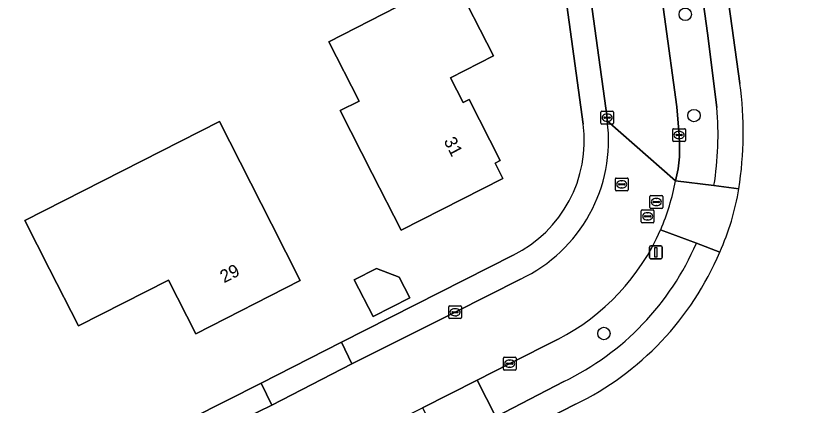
# Model space of a CAD drawing. Extents: x 162722 to 165104, y 384719 to 386284.
# Drawn here: x 164061.9 to 164123.8, y 385023.1 to 385053.7 of the extents above; entities that cross this region are included whole.
import ezdxf

# ---------------------------------------------------------------- set-up
doc = ezdxf.new("R2010")
doc.units = 0
for name, color, linetype in [('IMGEO_Boom', 7, 'Continuous'), ('IMGEO_Erf', 7, 'Continuous'), ('IMGEO_Groenvoorziening', 7, 'Continuous'), ('IMGEO_Kolk', 7, 'Continuous'), ('IMGEO_Lichtmast', 7, 'Continuous'), ('IMGEO_Pand', 7, 'Continuous'), ('IMGEO_Pand_nummerreeks', 7, 'Continuous'), ('IMGEO_Parkeervlak_open', 7, 'Continuous'), ('IMGEO_Rijbaan_lokaal_open', 7, 'Continuous'), ('IMGEO_Rioolput', 7, 'Continuous'), ('IMGEO_Voetpad_open', 7, 'Continuous')]:
    doc.layers.add(name, color=color, linetype=linetype)

msp = doc.modelspace()

# ---------------------------------------------------------------- linework, layer by layer
at = {"layer": 'IMGEO_Boom'}
for centre in [(164114.559, 385053.8), (164115.243, 385045.851), (164108.168, 385028.736)]:
    msp.add_circle(centre, 0.489, dxfattribs=at)
at = {"layer": 'IMGEO_Erf'}
for points in [[(164163.257, 385048.667), (164153.955, 385115.885), (164147.888, 385159.149), (164138.564, 385158), (164106.097, 385141.08), (164107.204, 385132.889), (164107.861, 385128.069), (164109.929, 385113.435), (164111.013, 385105.498), (164114.568, 385079.483), (164115.377, 385073.493), (164118.85, 385048.373)], [(164106.536, 385045.173), (164104.891, 385057.208)], [(164045.615, 385006.994), (164045.661, 385006.844), (164057.382, 385012.776), (164064.675, 385016.487), (164081.225, 385024.845), (164087.541, 385028.05), (164101.037, 385034.899)], [(164105.943, 385023.18), (164100.563, 385020.442), (164096.277, 385018.243), (164085.388, 385012.719), (164080.225, 385010.11), (164060.269, 385000), (164056.001, 384997.838), (164051.623, 384995.596), (164027.937, 384983.596), (164021.461, 384980.283), (164001.447, 384970.146), (164000, 384969.419), (163995.555, 384967.187), (163991.381, 384965.08), (163982.898, 384961.628)]]:
    msp.add_lwpolyline(points, dxfattribs=at)
for points in [[(164086.555, 385051.648), (164091.931, 385054.383), (164096.387, 385056.649), (164099.494, 385050.541), (164096.118, 385048.824), (164097.107, 385046.88), (164097.581, 385047.121), (164100.028, 385042.31), (164099.622, 385042.103), (164100.224, 385040.92), (164092.225, 385036.851), (164089.958, 385041.308), (164087.45, 385046.24), (164088.924, 385046.99)], [(164077.954, 385045.391), (164082.043, 385037.351), (164084.31, 385032.894), (164076.09, 385028.713), (164073.946, 385032.929), (164066.882, 385029.336), (164064.615, 385033.793), (164062.669, 385037.617)], [(164088.556, 385032.943), (164090.3, 385033.83), (164092.09, 385033.167), (164092.92, 385031.535), (164090.023, 385030.06)]]:
    msp.add_lwpolyline(points, close=True, dxfattribs=at)
for centre, radius, start, end in [((164090.657, 385044.517), 28.455, 351.0633, 7.7875), ((164096.613, 385043.876), 10.008, 296.23784, 7.44771), ((164099.205, 385043.286), 19.821, 335.69148, 350.74088), ((164095.684, 385044.246), 23.431, 295.96562, 337.09639)]:
    msp.add_arc(centre, radius, start, end, dxfattribs=at)
at = {"layer": 'IMGEO_Groenvoorziening'}
for points in [[(164117.043, 385046.479), (164116.295, 385052.312), (164113.428, 385073.243), (164110.323, 385072.813), (164111.956, 385060.695), (164113.896, 385046.54), (164114.074, 385044.319), (164114.117, 385043.575), (164114.097, 385042.613), (164113.99, 385041.657), (164113.799, 385040.714), (164116.814, 385040.352)], [(164115.441, 385035.835), (164112.627, 385036.876)], [(164104.574, 385028.285), (164100.766, 385026.367), (164098.211, 385025.06), (164099.678, 385022.179), (164105.03, 385024.959)]]:
    msp.add_lwpolyline(points, dxfattribs=at)
for centre, radius, start, end in [((164092.131, 385044.342), 25.003, 350.81686, 4.90221), ((164096.389, 385044.027), 17.743, 297.4715, 336.23127), ((164095.584, 385044.422), 21.634, 295.88866, 336.61412)]:
    msp.add_arc(centre, radius, start, end, dxfattribs=at)
at = {"layer": 'IMGEO_Kolk'}
for p, q in [((164107.924, 385045.26), (164107.924, 385046.112)), ((164107.999, 385046.186), (164108.851, 385046.186)), ((164108.183, 385045.68), (164108.183, 385045.692)), ((164108.226, 385045.729), (164108.624, 385045.729)), ((164108.412, 385045.966), (164108.437, 385045.966)), ((164108.667, 385045.692), (164108.667, 385045.68)), ((164108.925, 385046.112), (164108.925, 385045.26)), ((164108.851, 385045.186), (164107.999, 385045.186)), ((164108.621, 385045.643), (164108.223, 385045.643)), ((164108.435, 385045.406), (164108.41, 385045.406)), ((164113.573, 385043.893), (164113.573, 385044.745)), ((164113.648, 385044.819), (164114.5, 385044.819)), ((164114.061, 385044.599), (164114.086, 385044.599)), ((164114.574, 385044.745), (164114.574, 385043.893)), ((164114.5, 385043.819), (164113.648, 385043.819)), ((164113.832, 385044.313), (164113.832, 385044.325)), ((164114.27, 385044.276), (164113.872, 385044.276)), ((164113.875, 385044.362), (164114.273, 385044.362)), ((164114.084, 385044.039), (164114.059, 385044.039)), ((164114.316, 385044.325), (164114.316, 385044.313)), ((164095.97, 385029.979), (164095.97, 385030.831)), ((164096.045, 385030.905), (164096.897, 385030.905)), ((164096.971, 385030.831), (164096.971, 385029.979)), ((164096.229, 385030.399), (164096.229, 385030.411)), ((164096.667, 385030.362), (164096.269, 385030.362)), ((164096.272, 385030.448), (164096.67, 385030.448)), ((164096.458, 385030.685), (164096.483, 385030.685)), ((164096.713, 385030.411), (164096.713, 385030.399)), ((164096.897, 385029.905), (164096.045, 385029.905)), ((164096.481, 385030.125), (164096.456, 385030.125)), ((164100.265, 385025.941), (164100.265, 385026.793)), ((164100.34, 385026.867), (164101.192, 385026.867)), ((164100.753, 385026.647), (164100.778, 385026.647)), ((164101.266, 385026.793), (164101.266, 385025.941)), ((164100.524, 385026.361), (164100.524, 385026.373)), ((164100.962, 385026.324), (164100.564, 385026.324)), ((164100.567, 385026.41), (164100.965, 385026.41)), ((164100.776, 385026.087), (164100.751, 385026.087)), ((164101.008, 385026.373), (164101.008, 385026.361)), ((164101.192, 385025.867), (164100.34, 385025.867))]:
    msp.add_line(p, q, dxfattribs=at)
for points in [[(164107.924, 385045.26), (164107.924, 385046.112)], [(164107.999, 385046.186), (164108.851, 385046.186)], [(164108.925, 385046.112), (164108.925, 385045.26)], [(164108.851, 385045.186), (164107.999, 385045.186)], [(164113.573, 385043.893), (164113.573, 385044.745)], [(164113.648, 385044.819), (164114.5, 385044.819)], [(164114.574, 385044.745), (164114.574, 385043.893)], [(164114.5, 385043.819), (164113.648, 385043.819)], [(164095.97, 385029.979), (164095.97, 385030.831)], [(164096.045, 385030.905), (164096.897, 385030.905)], [(164096.971, 385030.831), (164096.971, 385029.979)], [(164096.897, 385029.905), (164096.045, 385029.905)], [(164100.265, 385025.941), (164100.265, 385026.793)], [(164100.34, 385026.867), (164101.192, 385026.867)], [(164101.266, 385026.793), (164101.266, 385025.941)], [(164101.192, 385025.867), (164100.34, 385025.867)]]:
    msp.add_lwpolyline(points, dxfattribs=at)
for centre, radius, start, end in [((164108.001, 385046.11), 0.0765, 91.55205, 178.44795), ((164108.001, 385046.11), 0.0765, 91.55205, 178.44795), ((164108.223, 385045.689), 0.0403, 85.87752, 175.75265), ((164108.22, 385045.679), 0.0366, 178.93798, 274.71019), ((164108.624, 385045.686), 0.043, 264.86636, 352.45326), ((164108.628, 385045.691), 0.0386, 1.73085, 96.63898), ((164108.849, 385046.11), 0.0765, 1.55205, 88.44795), ((164108.849, 385046.11), 0.0765, 1.55205, 88.44795), ((164108.001, 385045.262), 0.0765, 181.55205, 268.44795), ((164108.001, 385045.262), 0.0765, 181.55205, 268.44795), ((164108.849, 385045.262), 0.0765, 271.55205, 358.44795), ((164108.849, 385045.262), 0.0765, 271.55205, 358.44795), ((164113.65, 385044.743), 0.0765, 91.55205, 178.44795), ((164113.65, 385044.743), 0.0765, 91.55205, 178.44795), ((164114.498, 385044.743), 0.0765, 1.55205, 88.44795), ((164114.498, 385044.743), 0.0765, 1.55205, 88.44795), ((164113.65, 385043.895), 0.0765, 181.55205, 268.44795), ((164113.65, 385043.895), 0.0765, 181.55205, 268.44795), ((164113.872, 385044.322), 0.0403, 85.87752, 175.75265), ((164113.869, 385044.312), 0.0366, 178.93798, 274.71019), ((164114.273, 385044.319), 0.043, 264.86636, 352.45326), ((164114.277, 385044.324), 0.0386, 1.73085, 96.63898), ((164114.498, 385043.895), 0.0765, 271.55205, 358.44795), ((164114.498, 385043.895), 0.0765, 271.55205, 358.44795), ((164096.047, 385030.829), 0.0765, 91.55205, 178.44795), ((164096.047, 385030.829), 0.0765, 91.55205, 178.44795), ((164096.895, 385030.829), 0.0765, 1.55205, 88.44795), ((164096.895, 385030.829), 0.0765, 1.55205, 88.44795), ((164096.269, 385030.408), 0.0403, 85.87752, 175.75265), ((164096.266, 385030.398), 0.0366, 178.93798, 274.71019), ((164096.67, 385030.405), 0.043, 264.86636, 352.45326), ((164096.674, 385030.41), 0.0386, 1.73085, 96.63898), ((164096.047, 385029.981), 0.0765, 181.55205, 268.44795), ((164096.047, 385029.981), 0.0765, 181.55205, 268.44795), ((164096.895, 385029.981), 0.0765, 271.55205, 358.44795), ((164096.895, 385029.981), 0.0765, 271.55205, 358.44795), ((164100.342, 385026.791), 0.0765, 91.55205, 178.44795), ((164100.342, 385026.791), 0.0765, 91.55205, 178.44795), ((164101.19, 385026.791), 0.0765, 1.55205, 88.44795), ((164101.19, 385026.791), 0.0765, 1.55205, 88.44795), ((164100.342, 385025.943), 0.0765, 181.55205, 268.44795), ((164100.342, 385025.943), 0.0765, 181.55205, 268.44795), ((164100.564, 385026.37), 0.0403, 85.87752, 175.75265), ((164100.561, 385026.36), 0.0366, 178.93798, 274.71019), ((164100.965, 385026.367), 0.043, 264.86636, 352.45326), ((164100.969, 385026.372), 0.0386, 1.73085, 96.63898), ((164101.19, 385025.943), 0.0765, 271.55205, 358.44795), ((164101.19, 385025.943), 0.0765, 271.55205, 358.44795)]:
    msp.add_arc(centre, radius, start, end, dxfattribs=at)
for centre, major_axis, ratio, start_param, end_param in [((164108.411, 385045.686), (-0.387, 0.002), 0.722429, 4.712389, 7.853982), ((164108.436, 385045.686), (-0.39, 0.002), 0.717154, 1.570796, 4.712389), ((164114.06, 385044.319), (-0.387, 0.002), 0.722429, 4.712389, 7.853982), ((164114.085, 385044.319), (-0.39, 0.002), 0.717154, 1.570796, 4.712389), ((164096.457, 385030.405), (-0.387, 0.002), 0.722429, 4.712389, 7.853982), ((164096.482, 385030.405), (-0.39, 0.002), 0.717154, 1.570796, 4.712389), ((164100.752, 385026.367), (-0.387, 0.002), 0.722429, 4.712389, 7.853982), ((164100.777, 385026.367), (-0.39, 0.002), 0.717154, 1.570796, 4.712389)]:
    msp.add_ellipse(centre, major_axis=major_axis, ratio=ratio, start_param=start_param, end_param=end_param, dxfattribs=at)
at = {"layer": 'IMGEO_Lichtmast'}
for p, q in [((164111.749, 385034.711), (164111.749, 385035.511)), ((164111.749, 385035.511), (164111.749, 385034.711)), ((164111.849, 385035.611), (164112.639, 385035.611)), ((164112.639, 385035.611), (164111.849, 385035.611)), ((164112.739, 385035.511), (164112.739, 385034.711)), ((164112.739, 385034.711), (164112.739, 385035.511)), ((164112.639, 385034.611), (164111.849, 385034.611)), ((164111.849, 385034.611), (164112.639, 385034.611))]:
    msp.add_line(p, q, dxfattribs=at)
msp.add_lwpolyline([(164112.169, 385035.486), (164112.319, 385035.486), (164112.319, 385034.736), (164112.169, 385034.736), (164112.169, 385035.486)], dxfattribs=at)
for centre, start, end in [((164111.849, 385035.511), 90, 180), ((164111.849, 385035.511), 90, 180), ((164112.639, 385035.511), 0, 90), ((164112.639, 385035.511), 360, 90), ((164111.849, 385034.711), 180, 270), ((164111.849, 385034.711), 180, 270), ((164112.639, 385034.711), 270, 0), ((164112.639, 385034.711), 270, 0)]:
    msp.add_arc(centre, 0.1, start, end, dxfattribs=at)
at = {"layer": 'IMGEO_Pand'}
for points in [[(164092.225, 385036.851), (164100.224, 385040.92), (164099.622, 385042.103), (164100.028, 385042.31), (164097.581, 385047.121), (164097.107, 385046.88), (164096.118, 385048.824), (164099.494, 385050.541), (164096.387, 385056.649), (164091.931, 385054.383), (164086.555, 385051.648), (164088.924, 385046.99), (164087.45, 385046.24), (164089.958, 385041.308)], [(164066.882, 385029.336), (164073.946, 385032.929), (164076.09, 385028.713), (164084.31, 385032.894), (164082.043, 385037.351), (164077.954, 385045.391), (164062.669, 385037.617), (164064.615, 385033.793)], [(164088.556, 385032.943), (164090.023, 385030.06), (164092.92, 385031.535), (164092.09, 385033.167), (164090.3, 385033.83)]]:
    msp.add_lwpolyline(points, close=True, dxfattribs=at)
at = {"layer": 'IMGEO_Parkeervlak_open'}
for points in [[(164108.436, 385045.432), (164108.425, 385045.686), (164106.788, 385057.445), (164104.891, 385057.208), (164106.536, 385045.173)], [(164101.037, 385034.899), (164087.541, 385028.05), (164088.372, 385026.349), (164096.471, 385030.405), (164101.609, 385033.009)]]:
    msp.add_lwpolyline(points, dxfattribs=at)
msp.add_lwpolyline([(164064.675, 385016.487), (164065.538, 385014.795), (164066.906, 385015.461), (164081.011, 385022.579), (164082.061, 385023.117), (164081.225, 385024.845)], close=True, dxfattribs=at)
for centre, radius, start, end in [((164096.613, 385043.876), 10.008, 296.23784, 7.44771), ((164096.506, 385043.901), 12.028, 295.10515, 7.31328)]:
    msp.add_arc(centre, radius, start, end, dxfattribs=at)
at = {"layer": 'IMGEO_Rijbaan_lokaal_open'}
for points in [[(164103.283, 385082.726), (164103.594, 385080.595), (164104.101, 385076.908), (164104.718, 385072.421), (164106.033, 385062.888), (164106.788, 385057.445), (164108.425, 385045.686), (164108.436, 385045.432), (164113.799, 385040.714), (164113.99, 385041.657), (164114.097, 385042.613), (164114.117, 385043.575), (164114.074, 385044.319), (164113.896, 385046.54), (164111.956, 385060.695), (164110.323, 385072.813), (164109.468, 385078.814), (164109.099, 385081.644), (164106.583, 385099.714)], [(164113.799, 385040.714), (164108.436, 385045.432)], [(164101.609, 385033.009), (164096.471, 385030.405), (164088.372, 385026.349), (164082.061, 385023.117), (164081.011, 385022.579), (164066.906, 385015.461), (164065.538, 385014.795), (164058.234, 385011.087), (164052.18, 385007.948), (164046.901, 385005.343), (164046.648, 385005.238), (164034.319, 384998.907), (164034.19, 384998.857), (164031.839, 384997.657), (164016.722, 384989.956), (164015.73, 384989.449), (164012.885, 384988.012), (164002.685, 384982.806), (164000, 384981.448), (163998.758, 384980.82), (163995.493, 384979.191), (163988.741, 384975.747), (163986.456, 384974.572)], [(163989.052, 384969.703), (163993.208, 384971.822), (163999.171, 384974.857), (164000, 384975.271), (164000.843, 384975.693), (164016.445, 384983.616), (164019.048, 384984.967), (164025.477, 384988.187), (164048.752, 385000), (164049.239, 385000.247), (164053.614, 385002.474), (164054.784, 385003.095), (164069.482, 385010.558), (164077.864, 385014.778), (164083.036, 385017.376), (164084.605, 385018.186), (164093.91, 385022.896), (164098.211, 385025.06), (164100.766, 385026.367), (164104.574, 385028.285)]]:
    msp.add_lwpolyline(points, dxfattribs=at)
for centre, radius, start, end in [((164096.506, 385043.901), 12.028, 295.10515, 7.31328), ((164094.874, 385044.395), 19.28, 337.04531, 348.99277), ((164096.389, 385044.027), 17.743, 297.4715, 336.23127)]:
    msp.add_arc(centre, radius, start, end, dxfattribs=at)
at = {"layer": 'IMGEO_Rioolput'}
for p, q in [((164109.065, 385040.021), (164109.065, 385040.873)), ((164109.14, 385040.947), (164109.992, 385040.947)), ((164109.553, 385040.727), (164109.578, 385040.727)), ((164110.066, 385040.873), (164110.066, 385040.021)), ((164109.324, 385040.441), (164109.324, 385040.453)), ((164109.762, 385040.404), (164109.364, 385040.404)), ((164109.367, 385040.49), (164109.765, 385040.49)), ((164109.576, 385040.167), (164109.551, 385040.167)), ((164109.808, 385040.453), (164109.808, 385040.441)), ((164109.992, 385039.947), (164109.14, 385039.947)), ((164111.785, 385038.636), (164111.785, 385039.488)), ((164111.86, 385039.562), (164112.712, 385039.562)), ((164112.786, 385039.488), (164112.786, 385038.636)), ((164112.044, 385039.056), (164112.044, 385039.068)), ((164112.482, 385039.019), (164112.084, 385039.019)), ((164112.087, 385039.105), (164112.485, 385039.105)), ((164112.273, 385039.342), (164112.298, 385039.342)), ((164112.528, 385039.068), (164112.528, 385039.056)), ((164111.101, 385037.511), (164111.101, 385038.363)), ((164111.176, 385038.437), (164112.028, 385038.437)), ((164112.712, 385038.562), (164111.86, 385038.562)), ((164112.102, 385038.363), (164112.102, 385037.511)), ((164112.296, 385038.782), (164112.271, 385038.782)), ((164111.36, 385037.931), (164111.36, 385037.943)), ((164111.798, 385037.894), (164111.4, 385037.894)), ((164111.403, 385037.98), (164111.801, 385037.98)), ((164111.612, 385037.657), (164111.587, 385037.657)), ((164111.589, 385038.217), (164111.614, 385038.217)), ((164111.844, 385037.943), (164111.844, 385037.931)), ((164112.028, 385037.437), (164111.176, 385037.437))]:
    msp.add_line(p, q, dxfattribs=at)
for points in [[(164109.065, 385040.021), (164109.065, 385040.873)], [(164109.14, 385040.947), (164109.992, 385040.947)], [(164110.066, 385040.873), (164110.066, 385040.021)], [(164109.992, 385039.947), (164109.14, 385039.947)], [(164111.785, 385038.636), (164111.785, 385039.488)], [(164111.86, 385039.562), (164112.712, 385039.562)], [(164112.786, 385039.488), (164112.786, 385038.636)], [(164111.101, 385037.511), (164111.101, 385038.363)], [(164111.176, 385038.437), (164112.028, 385038.437)], [(164112.712, 385038.562), (164111.86, 385038.562)], [(164112.102, 385038.363), (164112.102, 385037.511)], [(164112.028, 385037.437), (164111.176, 385037.437)]]:
    msp.add_lwpolyline(points, dxfattribs=at)
for centre, radius, start, end in [((164109.142, 385040.871), 0.0765, 91.55205, 178.44795), ((164109.142, 385040.871), 0.0765, 91.55205, 178.44795), ((164109.99, 385040.871), 0.0765, 1.55205, 88.44795), ((164109.99, 385040.871), 0.0765, 1.55205, 88.44795), ((164109.364, 385040.45), 0.0403, 85.87752, 175.75265), ((164109.361, 385040.44), 0.0366, 178.93798, 274.71019), ((164109.765, 385040.447), 0.043, 264.86636, 352.45326), ((164109.769, 385040.452), 0.0386, 1.73085, 96.63898), ((164109.142, 385040.023), 0.0765, 181.55205, 268.44795), ((164109.142, 385040.023), 0.0765, 181.55205, 268.44795), ((164109.99, 385040.023), 0.0765, 271.55205, 358.44795), ((164109.99, 385040.023), 0.0765, 271.55205, 358.44795), ((164111.862, 385039.486), 0.0765, 91.55205, 178.44795), ((164111.862, 385039.486), 0.0765, 91.55205, 178.44795), ((164112.71, 385039.486), 0.0765, 1.55205, 88.44795), ((164112.71, 385039.486), 0.0765, 1.55205, 88.44795), ((164112.084, 385039.065), 0.0403, 85.87752, 175.75265), ((164112.081, 385039.055), 0.0366, 178.93798, 274.71019), ((164112.485, 385039.062), 0.043, 264.86636, 352.45326), ((164112.489, 385039.067), 0.0386, 1.73085, 96.63898), ((164111.178, 385038.361), 0.0765, 91.55205, 178.44795), ((164111.178, 385038.361), 0.0765, 91.55205, 178.44795), ((164111.862, 385038.638), 0.0765, 181.55205, 268.44795), ((164111.862, 385038.638), 0.0765, 181.55205, 268.44795), ((164112.026, 385038.361), 0.0765, 1.55205, 88.44795), ((164112.026, 385038.361), 0.0765, 1.55205, 88.44795), ((164112.71, 385038.638), 0.0765, 271.55205, 358.44795), ((164112.71, 385038.638), 0.0765, 271.55205, 358.44795), ((164111.4, 385037.94), 0.0403, 85.87752, 175.75265), ((164111.397, 385037.93), 0.0366, 178.93798, 274.71019), ((164111.801, 385037.937), 0.043, 264.86636, 352.45326), ((164111.805, 385037.942), 0.0386, 1.73085, 96.63898), ((164111.178, 385037.513), 0.0765, 181.55205, 268.44795), ((164111.178, 385037.513), 0.0765, 181.55205, 268.44795), ((164112.026, 385037.513), 0.0765, 271.55205, 358.44795), ((164112.026, 385037.513), 0.0765, 271.55205, 358.44795)]:
    msp.add_arc(centre, radius, start, end, dxfattribs=at)
for centre, major_axis, ratio, start_param, end_param in [((164109.552, 385040.447), (-0.387, 0.002), 0.722429, 4.712389, 7.853982), ((164109.577, 385040.447), (-0.39, 0.002), 0.717154, 1.570796, 4.712389), ((164112.272, 385039.062), (-0.387, 0.002), 0.722429, 4.712389, 7.853982), ((164112.297, 385039.062), (-0.39, 0.002), 0.717154, 1.570796, 4.712389), ((164111.588, 385037.937), (-0.387, 0.002), 0.722429, 4.712389, 7.853982), ((164111.613, 385037.937), (-0.39, 0.002), 0.717154, 1.570796, 4.712389)]:
    msp.add_ellipse(centre, major_axis=major_axis, ratio=ratio, start_param=start_param, end_param=end_param, dxfattribs=at)
at = {"layer": 'IMGEO_Voetpad_open'}
for points in [[(164118.85, 385048.373), (164115.377, 385073.493), (164113.428, 385073.243), (164116.295, 385052.312), (164117.043, 385046.479)], [(164118.767, 385040.097), (164116.814, 385040.352), (164113.799, 385040.714)], [(164116.814, 385040.352), (164118.767, 385040.097)], [(164112.627, 385036.876), (164115.441, 385035.835), (164117.268, 385035.127)], [(164117.268, 385035.127), (164115.441, 385035.835)], [(164105.03, 385024.959), (164099.678, 385022.179), (164100.563, 385020.442), (164105.943, 385023.18)]]:
    msp.add_lwpolyline(points, dxfattribs=at)
for points in [[(164088.372, 385026.349), (164087.541, 385028.05), (164081.225, 385024.845), (164082.061, 385023.117)], [(164095.367, 385020.004), (164096.277, 385018.243), (164100.563, 385020.442), (164099.678, 385022.179), (164098.211, 385025.06), (164093.91, 385022.896)]]:
    msp.add_lwpolyline(points, close=True, dxfattribs=at)
for centre, radius, start, end in [((164090.657, 385044.517), 28.455, 351.0633, 7.7875), ((164092.131, 385044.342), 25.003, 350.81686, 4.90221), ((164094.874, 385044.395), 19.28, 337.04531, 348.99277), ((164099.205, 385043.286), 19.821, 335.69148, 350.74088), ((164095.584, 385044.422), 21.634, 295.88866, 336.61412), ((164095.684, 385044.246), 23.431, 295.96562, 337.09639)]:
    msp.add_arc(centre, radius, start, end, dxfattribs=at)

# ---------------------------------------------------------------- texts
at = {"layer": 'IMGEO_Pand_nummerreeks'}
for s, rotation, p in [('31', 296.95907, (164095.558, 385043.864)), ('29', 26.95959, (164078.321, 385032.675))]:
    msp.add_text(s, height=1, rotation=rotation, dxfattribs=at).set_placement(p)

doc.saveas('drawing.dxf')
